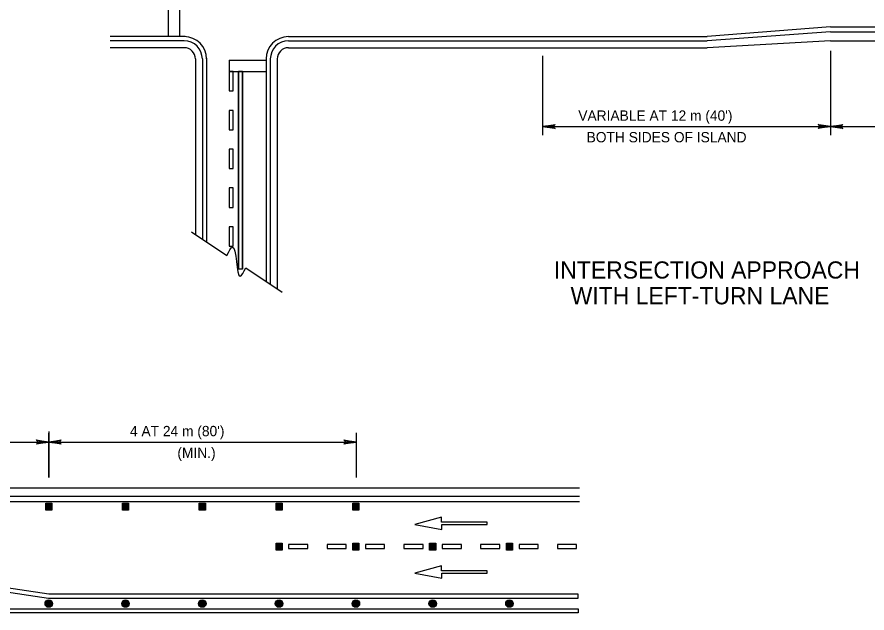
# Model space of a CAD drawing. Extents: x 639362 to 641108, y 298458 to 299646.
# Drawn here: x 639788.7 to 640036.4, y 298755.1 to 298928.7 of the extents above; entities that cross this region are included whole.
import ezdxf

# ---------------------------------------------------------------- set-up
doc = ezdxf.new("R2010")
doc.units = 0
doc.layers.add('2', color=7, linetype='Continuous')
doc.layers.add('3', color=7, linetype='Continuous')

# ---------------------------------------------------------------- blocks, each defined once
blk = doc.blocks.new('RARROW')
at = {"layer": '3'}
blk.add_lwpolyline([(-2.2695, 0.285), (-2.184875, 0.12075), (0, 0), (-2.2695, 0.285), (-2.38575, 0.384625), (0, 0), (-2.183125, -0.108), (-2.262875, -0.2705), (0, 0), (-2.38575, -0.379125), (-2.262875, -0.2705)], dxfattribs=at)

msp = doc.modelspace()

# ---------------------------------------------------------------- linework, layer by layer
at = {"layer": '2'}
for p, q in [((639832.85, 298922.95), (639832.85, 298950.59)), ((639836.15, 298922.95), (639836.15, 298950.59)), ((640025.73, 298925.85), (639989.83, 298922.95)), ((640025.73, 298925.85), (640169.33, 298925.85)), ((639837.77, 298922.95), (639815.93, 298922.95)), ((639867.83, 298922.95), (639989.83, 298922.95)), ((640025.73, 298924.35), (639989.83, 298921.72)), ((640025.73, 298924.35), (640169.33, 298924.35)), ((639837.47, 298921.72), (639815.93, 298921.72)), ((639837.47, 298919.72), (639815.93, 298919.72)), ((639867.83, 298921.72), (639989.83, 298921.72)), ((639867.83, 298919.72), (639989.83, 298919.72)), ((640025.73, 298921.72), (639989.83, 298919.72)), ((640025.73, 298921.72), (640169.33, 298921.72)), ((639941.89, 298917.32), (639941.89, 298894.23)), ((640025.73, 298918.79), (640025.73, 298894.23)), ((639840.75, 298916.44), (639840.75, 298865.35)), ((639842.75, 298916.44), (639842.75, 298864.01)), ((639843.98, 298916.69), (639843.98, 298863.19)), ((639850.53, 298916.09), (639850.53, 298912.79)), ((639850.53, 298916.09), (639861.32, 298916.09)), ((639861.32, 298916.53), (639861.32, 298851.64)), ((639862.55, 298916.44), (639862.55, 298850.81)), ((639864.55, 298916.44), (639864.55, 298849.48)), ((639850.53, 298912.79), (639861.32, 298912.79)), ((639854.47, 298912.79), (639853.27, 298912.79)), ((639853.27, 298912.79), (639853.27, 298855.27)), ((639853.27, 298855.27), (639853.27, 298912.79)), ((639853.27, 298912.79), (639854.47, 298912.79)), ((639854.47, 298855.27), (639854.47, 298912.79)), ((639854.47, 298912.79), (639854.47, 298855.27)), ((639941.89, 298896.78), (640025.73, 298896.78)), ((640025.73, 298896.78), (640169.33, 298896.78)), ((639839.62, 298866.1), (639849.91, 298859.24)), ((639854.47, 298855.27), (639853.27, 298855.27)), ((639855.4, 298855.58), (639866.03, 298848.49)), ((639797.99, 298807.92), (639797.99, 298794.58)), ((639798, 298794.58), (639798, 298807.5)), ((639887.61, 298794.58), (639887.61, 298807.59)), ((639585.52, 298804.88), (639797.99, 298804.88)), ((639798.01, 298804.88), (639887.61, 298804.88)), ((639431.25, 298791.58), (639952.64, 298791.58)), ((639789.19, 298791.58), (639951.12, 298791.58)), ((639431.25, 298789.08), (639952.64, 298789.08)), ((639789.84, 298789.08), (639951.12, 298789.08)), ((639431.25, 298787.58), (639952.64, 298787.58)), ((639790.24, 298787.58), (639951.12, 298787.58)), ((639797.11, 298785.06), (639797.11, 298787.1)), ((639797.11, 298787.1), (639798.88, 298787.1)), ((639797.28, 298785.23), (639797.28, 298786.92)), ((639797.28, 298786.92), (639798.7, 298786.92)), ((639797.46, 298785.41), (639797.46, 298786.74)), ((639797.46, 298786.74), (639798.53, 298786.74)), ((639797.64, 298785.59), (639797.64, 298786.56)), ((639797.64, 298786.56), (639798.35, 298786.56)), ((639797.82, 298785.76), (639797.82, 298786.39)), ((639797.82, 298786.39), (639798.17, 298786.39)), ((639798.17, 298785.76), (639797.82, 298785.76)), ((639798, 298785.94), (639798, 298786.21)), ((639798.17, 298786.39), (639798.17, 298785.76)), ((639798.35, 298786.56), (639798.35, 298785.59)), ((639798.53, 298786.74), (639798.53, 298785.41)), ((639798.7, 298786.92), (639798.7, 298785.23)), ((639798.88, 298787.1), (639798.88, 298785.06)), ((639819.47, 298785.06), (639819.47, 298787.1)), ((639819.47, 298787.1), (639821.25, 298787.1)), ((639819.65, 298785.23), (639819.65, 298786.92)), ((639819.65, 298786.92), (639821.07, 298786.92)), ((639819.83, 298785.41), (639819.83, 298786.74)), ((639819.83, 298786.74), (639820.89, 298786.74)), ((639820.01, 298785.59), (639820.01, 298786.56)), ((639820.01, 298786.56), (639820.72, 298786.56)), ((639820.18, 298785.76), (639820.18, 298786.39)), ((639820.18, 298786.39), (639820.54, 298786.39)), ((639820.54, 298785.76), (639820.18, 298785.76)), ((639820.36, 298785.94), (639820.36, 298786.21)), ((639820.54, 298786.39), (639820.54, 298785.76)), ((639820.72, 298786.56), (639820.72, 298785.59)), ((639820.89, 298786.74), (639820.89, 298785.41)), ((639821.07, 298786.92), (639821.07, 298785.23)), ((639821.25, 298787.1), (639821.25, 298785.06)), ((639841.84, 298785.06), (639841.84, 298787.1)), ((639841.84, 298787.1), (639843.62, 298787.1)), ((639842.02, 298785.23), (639842.02, 298786.92)), ((639842.02, 298786.92), (639843.44, 298786.92)), ((639842.2, 298785.41), (639842.2, 298786.74)), ((639842.2, 298786.74), (639843.26, 298786.74)), ((639842.37, 298785.59), (639842.37, 298786.56)), ((639842.37, 298786.56), (639843.08, 298786.56)), ((639842.55, 298785.76), (639842.55, 298786.39)), ((639842.55, 298786.39), (639842.91, 298786.39)), ((639842.91, 298785.76), (639842.55, 298785.76)), ((639842.73, 298785.94), (639842.73, 298786.21)), ((639842.91, 298786.39), (639842.91, 298785.76)), ((639843.08, 298786.56), (639843.08, 298785.59)), ((639843.26, 298786.74), (639843.26, 298785.41)), ((639843.44, 298786.92), (639843.44, 298785.23)), ((639843.62, 298787.1), (639843.62, 298785.06)), ((639864.21, 298785.06), (639864.21, 298787.1)), ((639864.21, 298787.1), (639865.98, 298787.1)), ((639864.39, 298785.23), (639864.39, 298786.92)), ((639864.39, 298786.92), (639865.81, 298786.92)), ((639864.56, 298785.41), (639864.56, 298786.74)), ((639864.56, 298786.74), (639865.63, 298786.74)), ((639864.74, 298785.59), (639864.74, 298786.56)), ((639864.74, 298786.56), (639865.45, 298786.56)), ((639864.92, 298785.76), (639864.92, 298786.39)), ((639864.92, 298786.39), (639865.27, 298786.39)), ((639865.27, 298785.76), (639864.92, 298785.76)), ((639865.1, 298785.94), (639865.1, 298786.21)), ((639865.27, 298786.39), (639865.27, 298785.76)), ((639865.45, 298786.56), (639865.45, 298785.59)), ((639865.63, 298786.74), (639865.63, 298785.41)), ((639865.81, 298786.92), (639865.81, 298785.23)), ((639865.98, 298787.1), (639865.98, 298785.06)), ((639886.58, 298785.06), (639886.58, 298787.1)), ((639886.58, 298787.1), (639888.35, 298787.1)), ((639886.75, 298785.23), (639886.75, 298786.92)), ((639886.75, 298786.92), (639888.17, 298786.92)), ((639886.93, 298785.41), (639886.93, 298786.74)), ((639886.93, 298786.74), (639888, 298786.74)), ((639887.11, 298785.59), (639887.11, 298786.56)), ((639887.11, 298786.56), (639887.82, 298786.56)), ((639887.29, 298785.76), (639887.29, 298786.39)), ((639887.29, 298786.39), (639887.64, 298786.39)), ((639887.64, 298785.76), (639887.29, 298785.76)), ((639887.47, 298785.94), (639887.47, 298786.21)), ((639887.64, 298786.39), (639887.64, 298785.76)), ((639887.82, 298786.56), (639887.82, 298785.59)), ((639888, 298786.74), (639888, 298785.41)), ((639888.17, 298786.92), (639888.17, 298785.23)), ((639888.35, 298787.1), (639888.35, 298785.06)), ((639798.88, 298785.06), (639797.11, 298785.06)), ((639798.7, 298785.23), (639797.28, 298785.23)), ((639798.53, 298785.41), (639797.46, 298785.41)), ((639798.35, 298785.59), (639797.64, 298785.59)), ((639821.25, 298785.06), (639819.47, 298785.06)), ((639821.07, 298785.23), (639819.65, 298785.23)), ((639820.89, 298785.41), (639819.83, 298785.41)), ((639820.72, 298785.59), (639820.01, 298785.59)), ((639843.62, 298785.06), (639841.84, 298785.06)), ((639843.44, 298785.23), (639842.02, 298785.23)), ((639843.26, 298785.41), (639842.2, 298785.41)), ((639843.08, 298785.59), (639842.37, 298785.59)), ((639865.98, 298785.06), (639864.21, 298785.06)), ((639865.81, 298785.23), (639864.39, 298785.23)), ((639865.63, 298785.41), (639864.56, 298785.41)), ((639865.45, 298785.59), (639864.74, 298785.59)), ((639888.35, 298785.06), (639886.58, 298785.06)), ((639888.17, 298785.23), (639886.75, 298785.23)), ((639888, 298785.41), (639886.93, 298785.41)), ((639887.82, 298785.59), (639887.11, 298785.59)), ((639912.39, 298782.98), (639904.67, 298780.86)), ((639904.67, 298780.86), (639912.47, 298779.39)), ((639912.39, 298781.54), (639912.39, 298782.98)), ((639925.72, 298781.54), (639912.39, 298781.54)), ((639912.47, 298779.39), (639912.47, 298780.83)), ((639912.47, 298780.83), (639925.72, 298780.83)), ((639925.72, 298780.83), (639925.72, 298781.54)), ((639864.21, 298773.41), (639864.21, 298775.45)), ((639864.21, 298775.45), (639865.98, 298775.45)), ((639865.98, 298773.41), (639864.21, 298773.41)), ((639864.39, 298773.59), (639864.39, 298775.27)), ((639864.39, 298775.27), (639865.81, 298775.27)), ((639865.81, 298773.59), (639864.39, 298773.59)), ((639864.56, 298773.77), (639864.56, 298775.09)), ((639864.56, 298775.09), (639865.63, 298775.09)), ((639865.63, 298773.77), (639864.56, 298773.77)), ((639864.74, 298773.94), (639864.74, 298774.92)), ((639864.74, 298774.92), (639865.45, 298774.92)), ((639865.45, 298773.94), (639864.74, 298773.94)), ((639864.92, 298774.12), (639864.92, 298774.74)), ((639864.92, 298774.74), (639865.27, 298774.74)), ((639865.27, 298774.12), (639864.92, 298774.12)), ((639865.1, 298774.29), (639865.1, 298774.56)), ((639865.27, 298774.74), (639865.27, 298774.12)), ((639865.45, 298774.92), (639865.45, 298773.94)), ((639865.63, 298775.09), (639865.63, 298773.77)), ((639865.81, 298775.27), (639865.81, 298773.59)), ((639865.98, 298775.45), (639865.98, 298773.41)), ((639873.49, 298775.03), (639867.89, 298775.03)), ((639867.89, 298775.03), (639867.89, 298773.83)), ((639867.89, 298773.83), (639873.49, 298773.83)), ((639873.49, 298773.83), (639873.49, 298775.03)), ((639884.67, 298775.03), (639879.08, 298775.03)), ((639879.08, 298775.03), (639879.08, 298773.83)), ((639879.08, 298773.83), (639884.67, 298773.83)), ((639884.67, 298773.83), (639884.67, 298775.03)), ((639886.58, 298773.41), (639886.58, 298775.45)), ((639886.58, 298775.45), (639888.35, 298775.45)), ((639888.35, 298773.41), (639886.58, 298773.41)), ((639886.75, 298773.59), (639886.75, 298775.27)), ((639886.75, 298775.27), (639888.17, 298775.27)), ((639888.17, 298773.59), (639886.75, 298773.59)), ((639886.93, 298773.77), (639886.93, 298775.09)), ((639886.93, 298775.09), (639888, 298775.09)), ((639888, 298773.77), (639886.93, 298773.77)), ((639887.11, 298773.94), (639887.11, 298774.92)), ((639887.11, 298774.92), (639887.82, 298774.92)), ((639887.82, 298773.94), (639887.11, 298773.94)), ((639887.29, 298774.12), (639887.29, 298774.74)), ((639887.29, 298774.74), (639887.64, 298774.74)), ((639887.64, 298774.12), (639887.29, 298774.12)), ((639887.47, 298774.29), (639887.47, 298774.56)), ((639887.64, 298774.74), (639887.64, 298774.12)), ((639887.82, 298774.92), (639887.82, 298773.94)), ((639888, 298775.09), (639888, 298773.77)), ((639888.17, 298775.27), (639888.17, 298773.59)), ((639888.35, 298775.45), (639888.35, 298773.41)), ((639895.85, 298775.03), (639890.26, 298775.03)), ((639890.26, 298775.03), (639890.26, 298773.83)), ((639890.26, 298773.83), (639895.85, 298773.83)), ((639895.85, 298773.83), (639895.85, 298775.03)), ((639907.04, 298775.03), (639901.45, 298775.03)), ((639901.45, 298775.03), (639901.45, 298773.83)), ((639901.45, 298773.83), (639907.04, 298773.83)), ((639907.04, 298773.83), (639907.04, 298775.03)), ((639908.94, 298773.41), (639908.94, 298775.45)), ((639908.94, 298775.45), (639910.72, 298775.45)), ((639910.72, 298773.41), (639908.94, 298773.41)), ((639909.12, 298773.59), (639909.12, 298775.27)), ((639909.12, 298775.27), (639910.54, 298775.27)), ((639910.54, 298773.59), (639909.12, 298773.59)), ((639909.3, 298773.77), (639909.3, 298775.09)), ((639909.3, 298775.09), (639910.36, 298775.09)), ((639910.36, 298773.77), (639909.3, 298773.77)), ((639909.48, 298773.94), (639909.48, 298774.92)), ((639909.48, 298774.92), (639910.19, 298774.92)), ((639910.19, 298773.94), (639909.48, 298773.94)), ((639909.65, 298774.12), (639909.65, 298774.74)), ((639909.65, 298774.74), (639910.01, 298774.74)), ((639910.01, 298774.12), (639909.65, 298774.12)), ((639909.83, 298774.29), (639909.83, 298774.56)), ((639910.01, 298774.74), (639910.01, 298774.12)), ((639910.19, 298774.92), (639910.19, 298773.94)), ((639910.36, 298775.09), (639910.36, 298773.77)), ((639910.54, 298775.27), (639910.54, 298773.59)), ((639910.72, 298775.45), (639910.72, 298773.41)), ((639918.22, 298775.03), (639912.63, 298775.03)), ((639912.63, 298775.03), (639912.63, 298773.83)), ((639912.63, 298773.83), (639918.22, 298773.83)), ((639918.22, 298773.83), (639918.22, 298775.03)), ((639929.41, 298775.03), (639923.81, 298775.03)), ((639923.81, 298775.03), (639923.81, 298773.83)), ((639923.81, 298773.83), (639929.41, 298773.83)), ((639929.41, 298773.83), (639929.41, 298775.03)), ((639931.31, 298773.41), (639931.31, 298775.45)), ((639931.31, 298775.45), (639933.09, 298775.45)), ((639933.09, 298773.41), (639931.31, 298773.41)), ((639931.49, 298773.59), (639931.49, 298775.27)), ((639931.49, 298775.27), (639932.91, 298775.27)), ((639932.91, 298773.59), (639931.49, 298773.59)), ((639931.67, 298773.77), (639931.67, 298775.09)), ((639931.67, 298775.09), (639932.73, 298775.09)), ((639932.73, 298773.77), (639931.67, 298773.77)), ((639931.84, 298773.94), (639931.84, 298774.92)), ((639931.84, 298774.92), (639932.55, 298774.92)), ((639932.55, 298773.94), (639931.84, 298773.94)), ((639932.02, 298774.12), (639932.02, 298774.74)), ((639932.02, 298774.74), (639932.38, 298774.74)), ((639932.38, 298774.12), (639932.02, 298774.12)), ((639932.2, 298774.29), (639932.2, 298774.56)), ((639932.38, 298774.74), (639932.38, 298774.12)), ((639932.55, 298774.92), (639932.55, 298773.94)), ((639932.73, 298775.09), (639932.73, 298773.77)), ((639932.91, 298775.27), (639932.91, 298773.59)), ((639933.09, 298775.45), (639933.09, 298773.41)), ((639940.59, 298775.03), (639935, 298775.03)), ((639935, 298775.03), (639935, 298773.83)), ((639935, 298773.83), (639940.59, 298773.83)), ((639940.59, 298773.83), (639940.59, 298775.03)), ((639951.77, 298775.03), (639946.18, 298775.03)), ((639946.18, 298775.03), (639946.18, 298773.83)), ((639946.18, 298773.83), (639951.77, 298773.83)), ((639951.77, 298773.83), (639951.77, 298775.03)), ((639719.64, 298770.96), (639797.91, 298759.39)), ((639798, 298760.59), (639719.73, 298772.16)), ((639912.39, 298768.82), (639904.67, 298766.7)), ((639912.39, 298767.38), (639912.39, 298768.82)), ((639904.67, 298766.7), (639912.47, 298765.23)), ((639925.72, 298767.38), (639912.39, 298767.38)), ((639912.47, 298765.23), (639912.47, 298766.67)), ((639912.47, 298766.67), (639925.72, 298766.67)), ((639925.72, 298766.67), (639925.72, 298767.38)), ((639797.91, 298759.39), (639952.26, 298759.39)), ((639952.26, 298760.59), (639798, 298760.59)), ((639952.26, 298759.39), (639952.26, 298760.59)), ((639663.88, 298756.28), (639952.26, 298756.28)), ((639952.26, 298756.28), (639952.26, 298755.08)), ((639952.26, 298755.08), (639663.79, 298755.08))]:
    msp.add_line(p, q, dxfattribs=at)
for points in [[(639850.53, 298907.13), (639851.73, 298907.13), (639851.73, 298912.79), (639850.53, 298912.79)], [(639850.53, 298895.83), (639851.73, 298895.83), (639851.73, 298901.48), (639850.53, 298901.48)], [(639850.53, 298884.52), (639851.73, 298884.52), (639851.73, 298890.18), (639850.53, 298890.18)], [(639850.53, 298873.22), (639851.73, 298873.22), (639851.73, 298878.87), (639850.53, 298878.87)], [(639850.53, 298861.91), (639851.73, 298861.91), (639851.73, 298867.57), (639850.53, 298867.57)]]:
    msp.add_lwpolyline(points, close=True, dxfattribs=at)
for centre, radius in [((639798.01, 298757.83), 1.1), ((639798.01, 298757.83), 1.02), ((639798.01, 298757.83), 0.946), ((639798.01, 298757.83), 0.868), ((639798.01, 298757.83), 0.789), ((639798.01, 298757.83), 0.711), ((639798.01, 298757.83), 0.633), ((639820.36, 298757.83), 1.1), ((639820.36, 298757.83), 1.02), ((639820.36, 298757.83), 0.946), ((639820.36, 298757.83), 0.868), ((639820.36, 298757.83), 0.789), ((639820.36, 298757.83), 0.711), ((639820.36, 298757.83), 0.633), ((639842.73, 298757.83), 1.1), ((639842.73, 298757.83), 1.02), ((639842.73, 298757.83), 0.946), ((639842.73, 298757.83), 0.868), ((639842.73, 298757.83), 0.789), ((639842.73, 298757.83), 0.711), ((639842.73, 298757.83), 0.633), ((639865.1, 298757.83), 1.1), ((639865.1, 298757.83), 1.02), ((639865.1, 298757.83), 0.946), ((639865.1, 298757.83), 0.868), ((639865.1, 298757.83), 0.789), ((639865.1, 298757.83), 0.711), ((639865.1, 298757.83), 0.633), ((639887.47, 298757.83), 1.1), ((639887.47, 298757.83), 1.02), ((639887.47, 298757.83), 0.946), ((639887.47, 298757.83), 0.868), ((639887.47, 298757.83), 0.789), ((639887.47, 298757.83), 0.711), ((639887.47, 298757.83), 0.633), ((639909.85, 298757.83), 1.1), ((639909.85, 298757.83), 1.02), ((639909.85, 298757.83), 0.946), ((639909.85, 298757.83), 0.868), ((639909.85, 298757.83), 0.789), ((639909.85, 298757.83), 0.711), ((639909.85, 298757.83), 0.633), ((639932.22, 298757.83), 1.1), ((639932.22, 298757.83), 1.02), ((639932.22, 298757.83), 0.946), ((639932.22, 298757.83), 0.868), ((639932.22, 298757.83), 0.789), ((639932.22, 298757.83), 0.711), ((639932.22, 298757.83), 0.633), ((639798.01, 298757.83), 0.554), ((639798.01, 298757.83), 0.476), ((639798.01, 298757.83), 0.398), ((639798.01, 298757.83), 0.32), ((639798.01, 298757.83), 0.241), ((639798.01, 298757.83), 0.163), ((639798.01, 298757.83), 0.0846), ((639820.36, 298757.83), 0.554), ((639820.36, 298757.83), 0.476), ((639820.36, 298757.83), 0.398), ((639820.36, 298757.83), 0.32), ((639820.36, 298757.83), 0.241), ((639820.36, 298757.83), 0.163), ((639820.36, 298757.83), 0.0846), ((639842.73, 298757.83), 0.554), ((639842.73, 298757.83), 0.476), ((639842.73, 298757.83), 0.398), ((639842.73, 298757.83), 0.32), ((639842.73, 298757.83), 0.241), ((639842.73, 298757.83), 0.163), ((639842.73, 298757.83), 0.0846), ((639865.1, 298757.83), 0.554), ((639865.1, 298757.83), 0.476), ((639865.1, 298757.83), 0.398), ((639865.1, 298757.83), 0.32), ((639865.1, 298757.83), 0.241), ((639865.1, 298757.83), 0.163), ((639865.1, 298757.83), 0.0846), ((639887.47, 298757.83), 0.554), ((639887.47, 298757.83), 0.476), ((639887.47, 298757.83), 0.398), ((639887.47, 298757.83), 0.32), ((639887.47, 298757.83), 0.241), ((639887.47, 298757.83), 0.163), ((639887.47, 298757.83), 0.0846), ((639909.85, 298757.83), 0.554), ((639909.85, 298757.83), 0.476), ((639909.85, 298757.83), 0.398), ((639909.85, 298757.83), 0.32), ((639909.85, 298757.83), 0.241), ((639909.85, 298757.83), 0.163), ((639909.85, 298757.83), 0.0846), ((639932.22, 298757.83), 0.554), ((639932.22, 298757.83), 0.476), ((639932.22, 298757.83), 0.398), ((639932.22, 298757.83), 0.32), ((639932.22, 298757.83), 0.241), ((639932.22, 298757.83), 0.163), ((639932.22, 298757.83), 0.0846)]:
    msp.add_circle(centre, radius, dxfattribs=at)
for centre, radius, start, end in [((639837.47, 298916.44), 6.52, 0, 90), ((639867.83, 298916.44), 6.52, 90, 180), ((639837.47, 298916.44), 5.28, 0, 90), ((639837.47, 298916.44), 3.28, 0, 90), ((639867.83, 298916.44), 5.28, 90, 180), ((639867.83, 298916.44), 3.28, 90, 180)]:
    msp.add_arc(centre, radius, start, end, dxfattribs=at)
msp.add_spline([(639849.91, 298859.24), (639851.51, 298861.66), (639853.8, 298853.18), (639855.4, 298855.58)], degree=3, dxfattribs=at)

# ---------------------------------------------------------------- block references
at = {"layer": '2', "xscale": 1.5089217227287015, "yscale": 1.5711553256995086, "rotation": 180}
for p in [(639941.89, 298896.78), (640025.73, 298896.78), (639798.01, 298804.88)]:
    msp.add_blockref('RARROW', p, dxfattribs=at)
at = {"layer": '2', "xscale": 1.5089217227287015, "yscale": 1.5711553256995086}
for p in [(640025.73, 298896.78), (639797.99, 298804.88), (639887.61, 298804.88)]:
    msp.add_blockref('RARROW', p, dxfattribs=at)

# ---------------------------------------------------------------- texts
at = {"layer": '2'}
for s, height, p in [("VARIABLE AT 12 m (40')", 3, (639952.27, 298898.46)), ('BOTH SIDES OF ISLAND', 3, (639954.7, 298892.17)), ('INTERSECTION APPROACH', 5, (639945.16, 298852.49)), ('WITH LEFT-TURN LANE', 5, (639950.04, 298844.99)), ("4 AT 24 m (80')", 3, (639821.66, 298806.57)), ('(MIN.)', 3, (639835.47, 298800.27))]:
    msp.add_text(s, height=height, dxfattribs=at).set_placement(p)

doc.saveas('drawing.dxf')
